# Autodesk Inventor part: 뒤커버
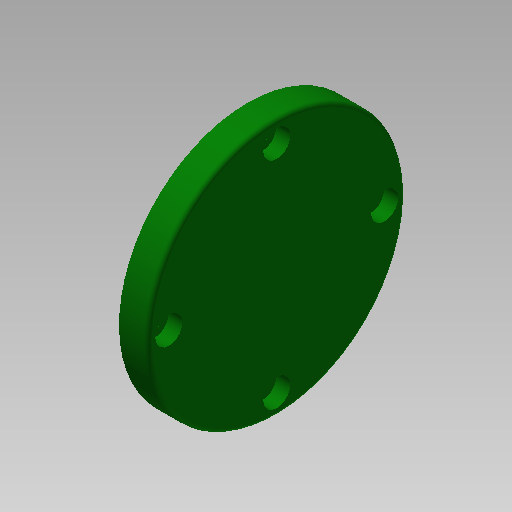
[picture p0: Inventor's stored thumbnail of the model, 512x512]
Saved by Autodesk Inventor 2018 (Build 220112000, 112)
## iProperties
Created: 2015-09
Part Number: 뒤커버
Material: 알루미늄 6061
Document SubType Name: Modeling
Designer: mduedu
Density: 2.71 g/cm^3
Mass: 54.0417 g
Surface Area: 84.9688 cm^2
Volume: 19.9416 cm^3
Appearance: 진녹색
Author: mduedu
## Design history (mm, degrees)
sketch "스케치1"
  geometry: L1 (-15.5, 47)-(-15.5, 78); L2 (-15.5, 78)-(-22.5, 78); L3 (-22.5, 78)-(-22.5, 67); L4 (-25.5, 67)-(-25.5, 47); L5 (-79.5, 39.5)-(-79.5, 54.5) reference; L6 (48.5, 54.5)-(48.5, 39.5) reference; L7 (-79.5, 47)-(48.5, 47); L8 (-22.5, 67)-(-25.5, 67); L9 (-25.5, 47)-(-15.5, 47); 1 further point
  constraints: 14 end point, 4 midpoint, 3 parallel, 1 collinear, 1 point on line, 1 vertical
  dimensions: "d6" = 62 diameter of L2 L7; "d7" = 7 distance of L1.end L2.end; "d8" = 40 diameter of L3.end L7; "d32" = 10 distance between parallel lines of L1 L4
revolve "회전1" sketch "스케치1" stored, may be unused: angle "d4" = 90 deg
sketch "스케치4"
  geometry: C1 r 31 at (0, 0) reference; 2 further points
  constraints: 1 coincident
hole "구멍3" sketch "스케치4" at (0, 0) diameter "d33" = 33; stored, may be unused: countersink angle "d37" = 90 deg, drill point angle "d39" = 0 deg; dims "d34" = 6, "d35" = 4, "d36" = 2, "d38" = 5
fillet "모깎기4" dims "d40" = 1, "d61" = 3
chamfer "모따기2" distance "d41" = 1; stored, may be unused: second distance "d42" = 2, angle "d43" = 45 deg
sketch "스케치6" dims "d56" = 52
  geometry: C1 r 31 at (0, 0) reference; 5 further points
  constraints: 2 vertical alignment, 1 coincident, 7 other
  dimensions: "d59" = 360 deg dimension on C1.centre point (0, 26) (derived)
hole "구멍4" sketch "스케치6" at (0, 26), (-26, 0), (0, -26), (26, 0) diameter "d49" = 3.4; stored, may be unused: countersink angle "d53" = 90 deg, drill point angle "d55" = 0 deg; dims "d50" = 6, "d51" = 6.5, "d52" = 3.4, "d54" = 8
node "솔리드1"
node "참조1"
node "참조2"
